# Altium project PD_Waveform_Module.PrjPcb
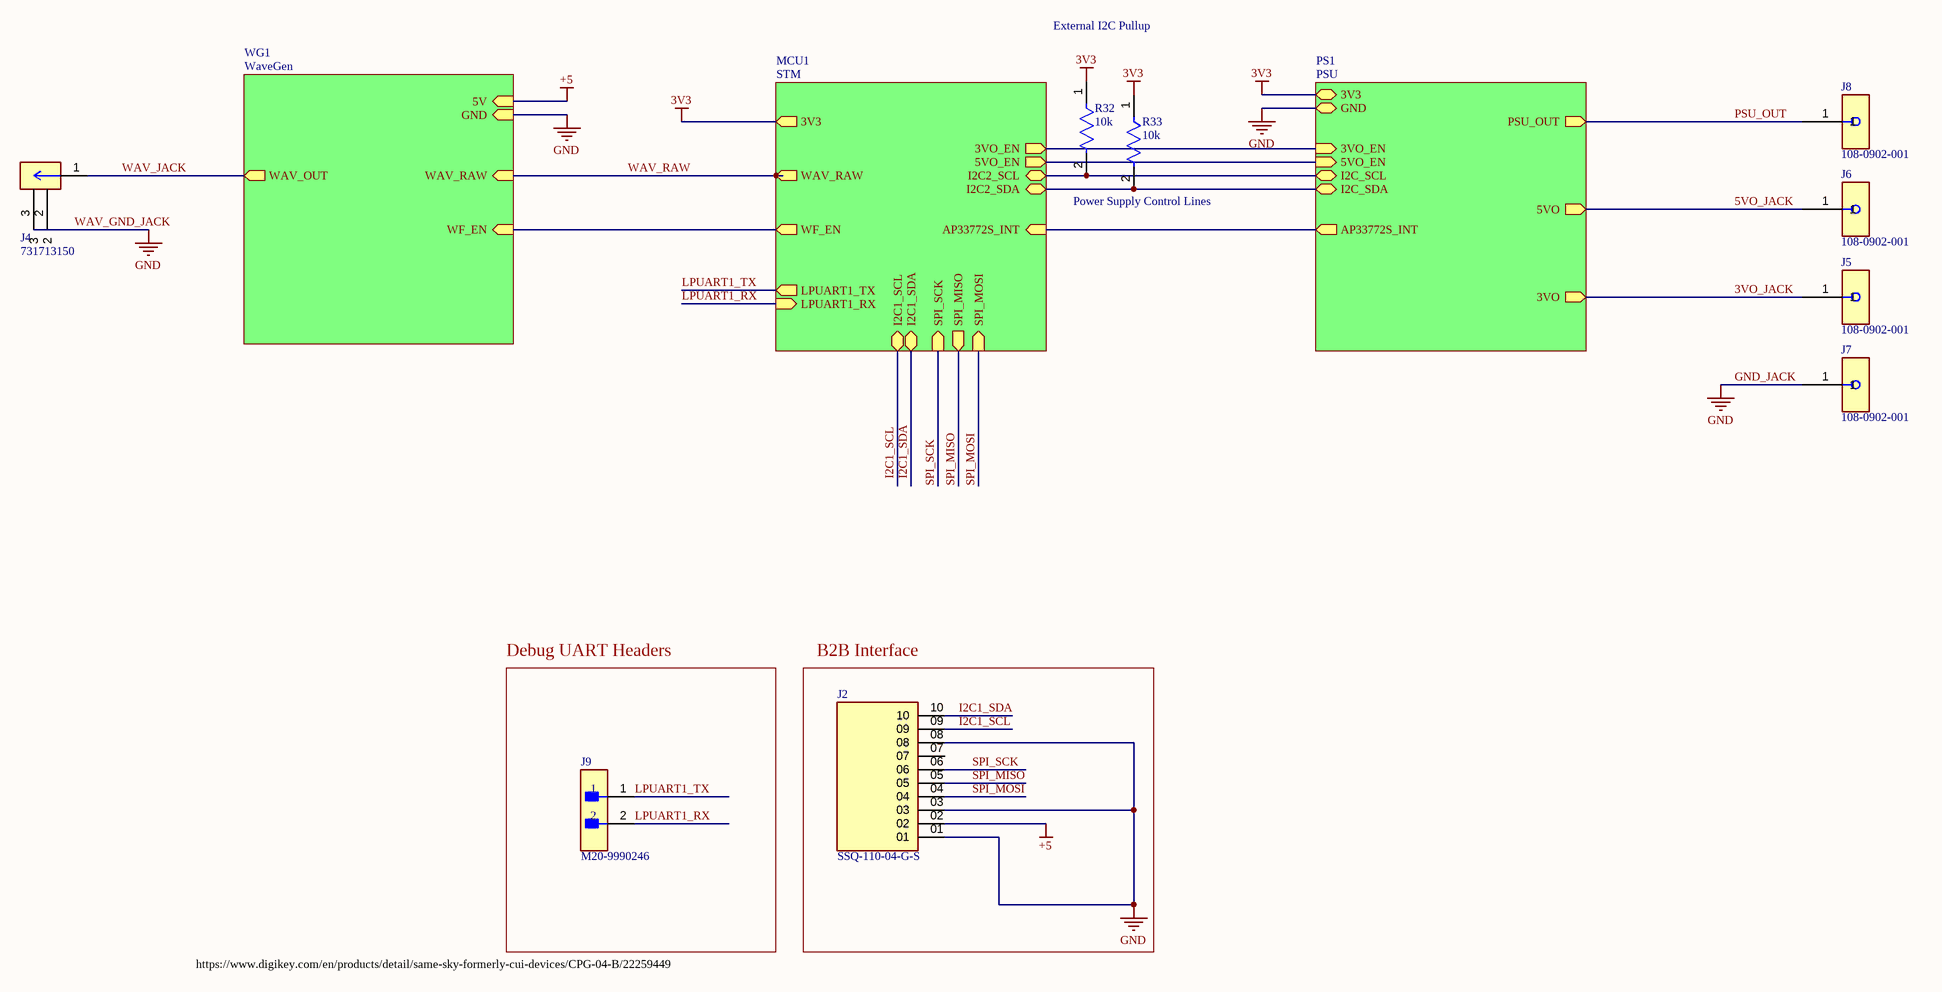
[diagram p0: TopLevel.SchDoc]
CAGE_CODE: ?????; CONTRACT_NUMBER: <CONTRACT NO>; DOC_NO_ASSY_DWG: <ASSY DWG NO>; DOC_NO_BOM: <BOM DOC NO>; DOC_NO_FAB_DWG: <FAB DWG NO>; DOC_NO_SCH_DWG: <SCH DWG NO>; PCB_2_DEC_TOL: +/-.01; PCB_3_DEC_TOL: +/-.010; PCB_ANG_TOL: +/-1/2; PCB_ASSEMBLY_NO: <PCB ASSY NO>; PCB_CHECKER: - -----; PCB_CHECKER_APP_DATE: --/--/----; PCB_DESIGNER: - -----; PCB_DESIGNER_APP_DATE: --/--/----; PCB_DWG_NO: <PCB DWG NO>; PCB_ENGINEER: - -----; PCB_ENGINEER_APP_DATE: --/--/----; PCB_PART_NUMBER: <PCB PN>; PCB_REV: A; SCH_REV: A
4 sheets, 96 parts. Net scope: hierarchical (ports join the sheet entries above them; power ports are global).
Board file: PCB1.PcbDoc
Sheets:
  TopLevel.SchDoc
    MCU1 = STM.SchDoc
    WG1 = WaveGen.SchDoc
    PS1 = PSU.SchDoc

## Sheet TopLevel.SchDoc
size 431 x 279 mm; SheetNumber: 1; SheetTotal: 4; ENG_APP_DATE: --/--/--; DSN_APP_DATE: --/--/--; CHK_APP_DATE: --/--/--

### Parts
J2  SSQ-110-04-G-S  [SAMTEC_SSQ-110-04-G-S]
J4  731713150  [CONN_731713150_MOL]
J5  108-0902-001  [FP-108-0902-001-MFG]
J6  108-0902-001  [FP-108-0902-001-MFG]
J7  108-0902-001  [FP-108-0902-001-MFG]
J8  108-0902-001  [FP-108-0902-001-MFG]
J9  M20-9990246  [FP-M20-9990246-MFG]
R32  10k  [FP-RC0603-0_55-IPC_C]
R33  10k  [FP-RC0603-0_55-IPC_C]

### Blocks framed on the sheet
Debug UART Headers: J9
B2B Interface: J2

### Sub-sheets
MCU1 = STM: 3VO_EN (out), 5VO_EN (out), I2C2_SCL (bidir), I2C2_SDA (bidir), AP33772S_INT (in), I2C1_SCL (bidir), I2C1_SDA (bidir), WAV_RAW (out), 3V3 (out), SPI_SCK (in), SPI_MISO (out), SPI_MOSI (in), LPUART1_TX (out), LPUART1_RX (in), WF_EN (out)
PS1 = PSU: I2C_SCL (bidir), AP33772S_INT (out), I2C_SDA (bidir), 3V3 (bidir), GND (bidir), 5VO_EN (in), 5VO (out), 3VO_EN (in), 3VO (out), PSU_OUT (out)
WG1 = WaveGen: WAV_OUT (out), WAV_RAW (in), 5V (in), GND (in), WF_EN (in)

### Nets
3V3: R32.1 R33.1 ; sheet MCU1/3V3, sheet PS1/3V3
+5: J2.02 ; sheet WG1/5V
GND: J2.01 J2.03 J2.08 J7.1 ; sheet WG1/GND, sheet PS1/GND  [also labelled GND_JACK, WAV_GND_JACK]
3VO_JACK: J5.1 ; sheet PS1/3VO
5VO_EN: sheet MCU1/5VO_EN, sheet PS1/5VO_EN
5VO_JACK: J6.1 ; sheet PS1/5VO  [project net 5VO]
I2C1_SCL: J2.09 ; sheet MCU1/I2C1_SCL
I2C1_SDA: J2.10 ; sheet MCU1/I2C1_SDA
I2C2_SCL: R32.2 ; sheet MCU1/I2C2_SCL, sheet PS1/I2C_SCL
I2C2_SDA: R33.2 ; sheet MCU1/I2C2_SDA, sheet PS1/I2C_SDA
LPUART1_RX: J9.2 ; sheet MCU1/LPUART1_RX
LPUART1_TX: J9.1 ; sheet MCU1/LPUART1_TX
PSU_OUT: J8.1 ; sheet PS1/PSU_OUT
SPI_MISO: J2.05 ; sheet MCU1/SPI_MISO
SPI_MOSI: J2.04 ; sheet MCU1/SPI_MOSI
SPI_SCK: J2.06 ; sheet MCU1/SPI_SCK
WAV_JACK: J4.1 ; sheet WG1/WAV_OUT
WAV_RAW: sheet MCU1/WAV_RAW, sheet WG1/WAV_RAW  [project net DAC1_OUT1]
NetQ6_1: sheet MCU1/WF_EN, sheet WG1/WF_EN
NetR9_1: sheet MCU1/AP33772S_INT, sheet PS1/AP33772S_INT
NetU1_39: sheet MCU1/3VO_EN, sheet PS1/3VO_EN

Not connected (* = marked no-connect by the designer): J2 07; J4 2 3

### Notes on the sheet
- External I2C Pullup
- Power Supply Control Lines
- https://www.digikey.com/en/products/detail/same-sky-formerly-cui-devices/CPG-04-B/22259449

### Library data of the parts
J2 = CMP-039-000000-3: Samtec Connector .1" pitch, long ahh pins
J4 = CMP-002-00084-4: JACK, BNC, 50OHM, R/A, THT; Connector Type: BNC Coaxial; Body Style: Right Angle J; MP: 73171-3150; MF: Molex
J5-J8 = CMP-002-00082-3: Banana Test Connector, 4mm, Jack, Panel Mount, 15 A, 7 kV, Tin Plated Contacts, Red; Gender: Female; Voltage Rating: 3.5kV; Max Current Rating: 15A
J9 = CMP-15831-000009-1: CONN HEADER VERT 2POS 2.54MM; Manufacturer: Harwin; Conn Gender: Male; Conn Orientation: Vertical; Number Of Contacts: 2; Current Rating: 3A
R32 R33 = CMP-2100-03664-2: RC0603FR-0710KL / RES 10K OHM 1% 1/10W 0603; Voltage Rating: 75V; Voltage Rating (DC): 50V; Resistance: 10kR; Power Rating: 100mW; Temperature Coefficient: 100ppm/°C

## Sheet STM.SchDoc
size A4; SheetNumber: 2; SheetTotal: 4
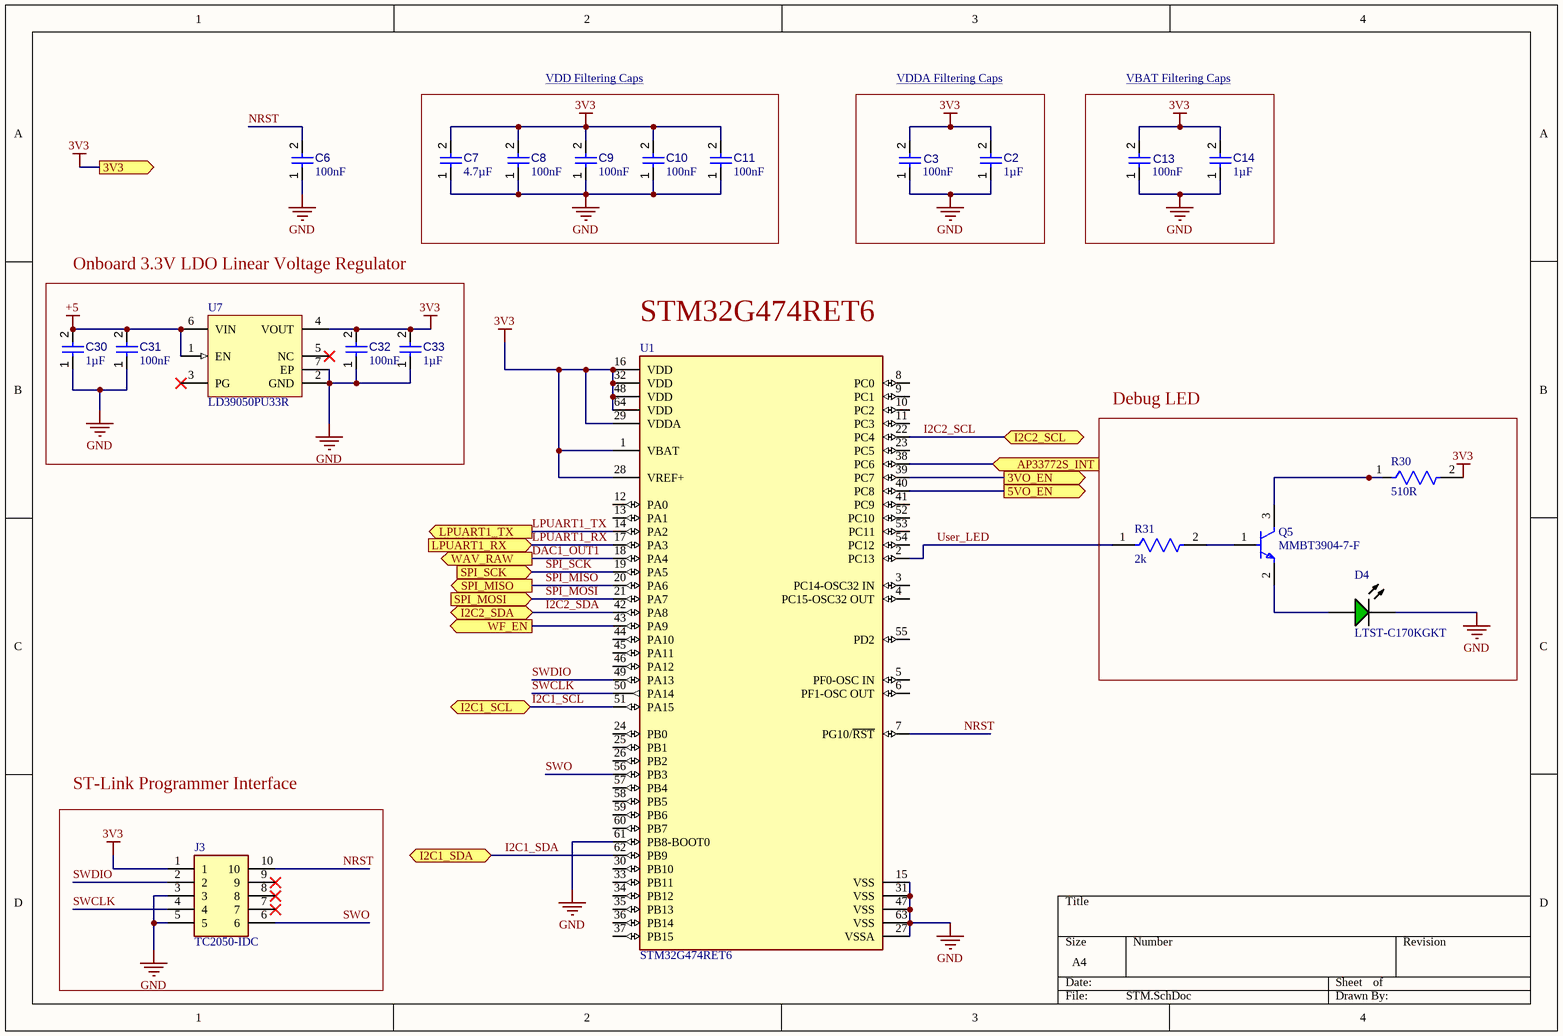
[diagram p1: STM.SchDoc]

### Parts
C2  value 1µF  [CAPC1608X90X35ML15T15]  (hidden comment: Capacitor 1uF +/- 10% 16V 0603)
C3  value 100nF  [CAPC0402(1005)60_L]  (hidden comment: Capacitor 100nF +/-20% 10V 0402)
C6  value 100nF  [CAPC1005X56X25LL10T15]  (hidden comment: Capacitor 0.1 uF +/- 5% 16 V 0402)
C7  value 4.7µF  [CAPC0603(1608)100_L]  (hidden comment: Capacitor 4.7µF +/-20% 10V 0603)
C8  value 100nF  [CAPC0402(1005)60_L]  (hidden comment: Capacitor 100nF +/-20% 10V 0402)
C9  value 100nF  [CAPC0402(1005)60_L]  (hidden comment: Capacitor 100nF +/-20% 10V 0402)
C10  value 100nF  [CAPC0402(1005)60_L]  (hidden comment: Capacitor 100nF +/-20% 10V 0402)
C11  value 100nF  [CAPC0402(1005)60_L]  (hidden comment: Capacitor 100nF +/-20% 10V 0402)
C13  value 100nF  [CAPC0402(1005)60_L]  (hidden comment: Capacitor 100nF +/-20% 10V 0402)
C14  value 1µF  [CAPC1608X90X35ML15T15]  (hidden comment: Capacitor 1uF +/- 10% 16V 0603)
C30  value 1µF  [CAPC1608X90X35ML15T15]  (hidden comment: Capacitor 1uF +/- 10% 16V 0603)
C31  value 100nF  [CAPC0402(1005)60_L]  (hidden comment: Capacitor 100nF +/-20% 10V 0402)
C32  value 100nF  [CAPC0402(1005)60_L]  (hidden comment: Capacitor 100nF +/-20% 10V 0402)
C33  value 1µF  [CAPC1608X90X35ML15T15]  (hidden comment: Capacitor 1uF +/- 10% 16V 0603)
D4  LTST-C170KGKT  [LTST-LTST-C170KGKT-2_V]
J3  TC2050-IDC  [TAG-CONNECT_TC2050-IDC]
Q5  MMBT3904-7-F  [FP-SOT23-IPC_A]
R30  510R  [FP-RMCF0603-IPC_B]
R31  2k  [FP-RMCF0603-IPC_C]
U1  STM32G474RET6  [FP-LQFP64-5W-MFG]
U7  LD39050PU33R  [DFN6D_M]

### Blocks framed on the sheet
VDD Filtering Caps: C7-C11
VDDA Filtering Caps: C2 C3
VBAT Filtering Caps: C13 C14
Onboard 3.3V LDO Linear Voltage Regulator: C30-C33 U7
Debug LED: D4 Q5 R30 R31
ST-Link Programmer Interface: J3

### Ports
3V3 (out), 3VO_EN (out), 5VO_EN (out), AP33772S_INT (in), I2C1_SCL (bidir), I2C1_SDA (bidir), I2C2_SCL (bidir), I2C2_SDA (bidir), LPUART1_RX (in), LPUART1_TX (out), SPI_MISO (out), SPI_MOSI (in), SPI_SCK (in), WAV_RAW (out), WF_EN (out)

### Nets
3V3: C2.2 C3.2 C7.2 C8.2 C9.2 C10.2 C11.2 C13.2 C14.2 C32.2 C33.2 J3.1 R30.2 U1.1(VBAT) U1.16(VDD) U1.28(VREF+) U1.29(VDDA) U1.32(VDD) U1.48(VDD) U1.64(VDD) U7.4(VOUT) ; port 3V3
+5: C30.2 C31.2 U7.1(EN) U7.6(VIN)
GND: C2.1 C3.1 C6.1 C7.1 C8.1 C9.1 C10.1 C11.1 C13.1 C14.1 C30.1 C31.1 C32.1 C33.1 D4.1(K) J3.3 J3.5 U1.15(VSS) U1.27(VSSA) U1.31(VSS) U1.47(VSS) U1.61(PB8-BOOT0) U1.63(VSS) U7.2(GND) U7.7(EP)
5VO_EN: U1.40(PC8) ; port 5VO_EN
DAC1_OUT1: U1.18(PA4) ; port WAV_RAW
I2C1_SCL: U1.51(PA15) ; port I2C1_SCL
I2C1_SDA: U1.62(PB9) ; port I2C1_SDA
I2C2_SCL: U1.22(PC4) ; port I2C2_SCL
I2C2_SDA: U1.42(PA8) ; port I2C2_SDA
LPUART1_RX: U1.17(PA3) ; port LPUART1_RX
LPUART1_TX: U1.14(PA2) ; port LPUART1_TX
NRST: C6.2 J3.10 U1.7(PG10/~{RST})
SPI_MISO: U1.20(PA6) ; port SPI_MISO
SPI_MOSI: U1.21(PA7) ; port SPI_MOSI
SPI_SCK: U1.19(PA5) ; port SPI_SCK
SWCLK: J3.4 U1.50(PA14)
SWDIO: J3.2 U1.49(PA13)
SWO: J3.6 U1.56(PB3)
User_LED: R31.1 U1.2(PC13)
NetD4_2: D4.2(A) Q5.2(E)
NetQ5_1: Q5.1(B) R31.2
NetQ5_3: Q5.3(C) R30.1
NetQ6_1: U1.43(PA9) ; port WF_EN
NetR9_1: U1.38(PC6) ; port AP33772S_INT
NetU1_39: U1.39(PC7) ; port 3VO_EN

Not connected (* = marked no-connect by the designer): J3 7* 8* 9*; U1 3(PC14-OSC32_IN) 4(PC15-OSC32_OUT) 5(PF0-OSC_IN) 6(PF1-OSC_OUT) 8(PC0) 9(PC1) 10(PC2) 11(PC3) 12(PA0) 13(PA1) 23(PC5) 24(PB0) 25(PB1) 26(PB2) 30(PB10) 33(PB11) 34(PB12) 35(PB13) 36(PB14) 37(PB15) 41(PC9) 44(PA10) 45(PA11) 46(PA12) 52(PC10) 53(PC11) 54(PC12) 55(PD2) 57(PB4) 58(PB5) 59(PB6) 60(PB7); U7 3(PG)* 5(NC)*

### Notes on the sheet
- (near U1) STM32G474RET6

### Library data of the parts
C2 C14 C30 C33 = CMP-001-00004-6: Chip Capacitor, 1 uF, +/- 10%, 16 V, 0603 (1608 Metric); Capacitor Type: Ceramic
C3 C8-C11 C13 C31 C32 = CMP-001-00061-3: Chip Capacitor, 100nF +/-20%, 10V, 0402, Thickness 0.6 mm; Tolerance: 20%
C6 = CMP-001-00001-6: Chip Capacitor, 0.1 uF, +/- 5%, 16 V, 0402 (1005 Metric); Capacitor Type: Ceramic; Voltage Rating: 16V
C7 = CMP-001-00076-4: Chip Capacitor, 4.7µF +/-20%, 10V, 0603, Thickness 1 mm; Tolerance: 10%
D4 = CMP-2000-06620-1: Ultra Bright AlInGaP Chip LED, 75 mW, -55 to 85 degC, 2-Pin SMD (0805), RoHS, Tape and Reel; Manufacturer: Lite-On; Forward Current: 30mA; Power Dissipation Max: 75mW; Emitting Color: YellowGreen; Type: Uni-Color; Forward Voltage: 2.4V; Dominant Wave Length: 571nm; Test Current (It): 20mA; Product Length (mm): 2mm; Peak Wavelength: 574nm; Power Dissipation: 75W; Product Depth (mm): 1.25mm; DELETED: Compliant; High Brightness: Yes; Product Height (mm): 1.1mm; Luminous Intensity: 35mcd; Shape Type: Rectangular; Chip Material: AlGaInP; Viewing Angle: 130deg; Number of  Elements: 1; Reverse Voltage: 5V; Rad Hardened: No
J3 = CMP-035-000000-1: Cbl Plug-Of-Nails 10-Pin w/Legs
Q5 = CMP-2000-04931-2: TRANS NPN 40V 0.2A SMD SOT23-3; Frequency: 300MHz; Power Dissipation: 350mW; Element Configuration: Single; Max Power Dissipation: 300mW; Max Collector Current: 200mA; Collector Emitter Saturation Voltage: 300mV; Number of Elements: 1; hFE Min: 100; Collector Base Voltage (VCBO): 60V; Emitter Base Voltage (VEBO): 6V
R30 = CMP-26527-005064-1: RMCF0603JG510R / 510Ω ±5% 0.1W 0603 Thick Film Chip Resistor AEC-Q200 compliant; Temperature Coefficient: 200ppm/°C; Max Power Dissipation: 100mW
R31 = CMP-26527-003372-1: RMCF0603FG2K00 / 2kΩ ±1% 0.1W 0603 Thick Film Chip Resistor AEC-Q200 compliant; Resistance: 2kR; Temperature Coefficient: 100ppm/°C
U1 = CMP-12105-000051-1: MAINSTREAM ARM CORTEX-M4 CORE WI; Manufacturer: STMicroelectronics; Ram Size: 128KBytes; Interface: I2C,SPI,UART,USART,CAN,USB,LIN,IrDA,I2S,SMBus,Other; Number Of I2C Channels: 4; Number Of A/D Converters: 5; Number Of Timers/Counters: 14; Number Of I/Os: 52; Max Supply Voltage: 3.6V; Memory Size: 512KBytes; Number Of Adc Channels: 26; Number Of Cores: 1; Min Supply Voltage: 1.71V; Max Junction Temp: +105°C; Standoff Height: 0.05mm; Number Of Uart Channels: 6; Number Of Spi Channels: 3; Frequency: 170MHz; Data Bus Width: 32bits; Memory Type: FLASH; Number Of Pwm Channels: 32
U7 = CMP-019-00050-2: 500 mA low quiescent current low noise voltage regulator; Max Supply Voltage: 5.5V; Output Current: 500mA; Dropout Voltage: 400mV; Output Voltage: 3.3V

## Sheet WaveGen.SchDoc
size A4; SheetNumber: 3; SheetTotal: 4
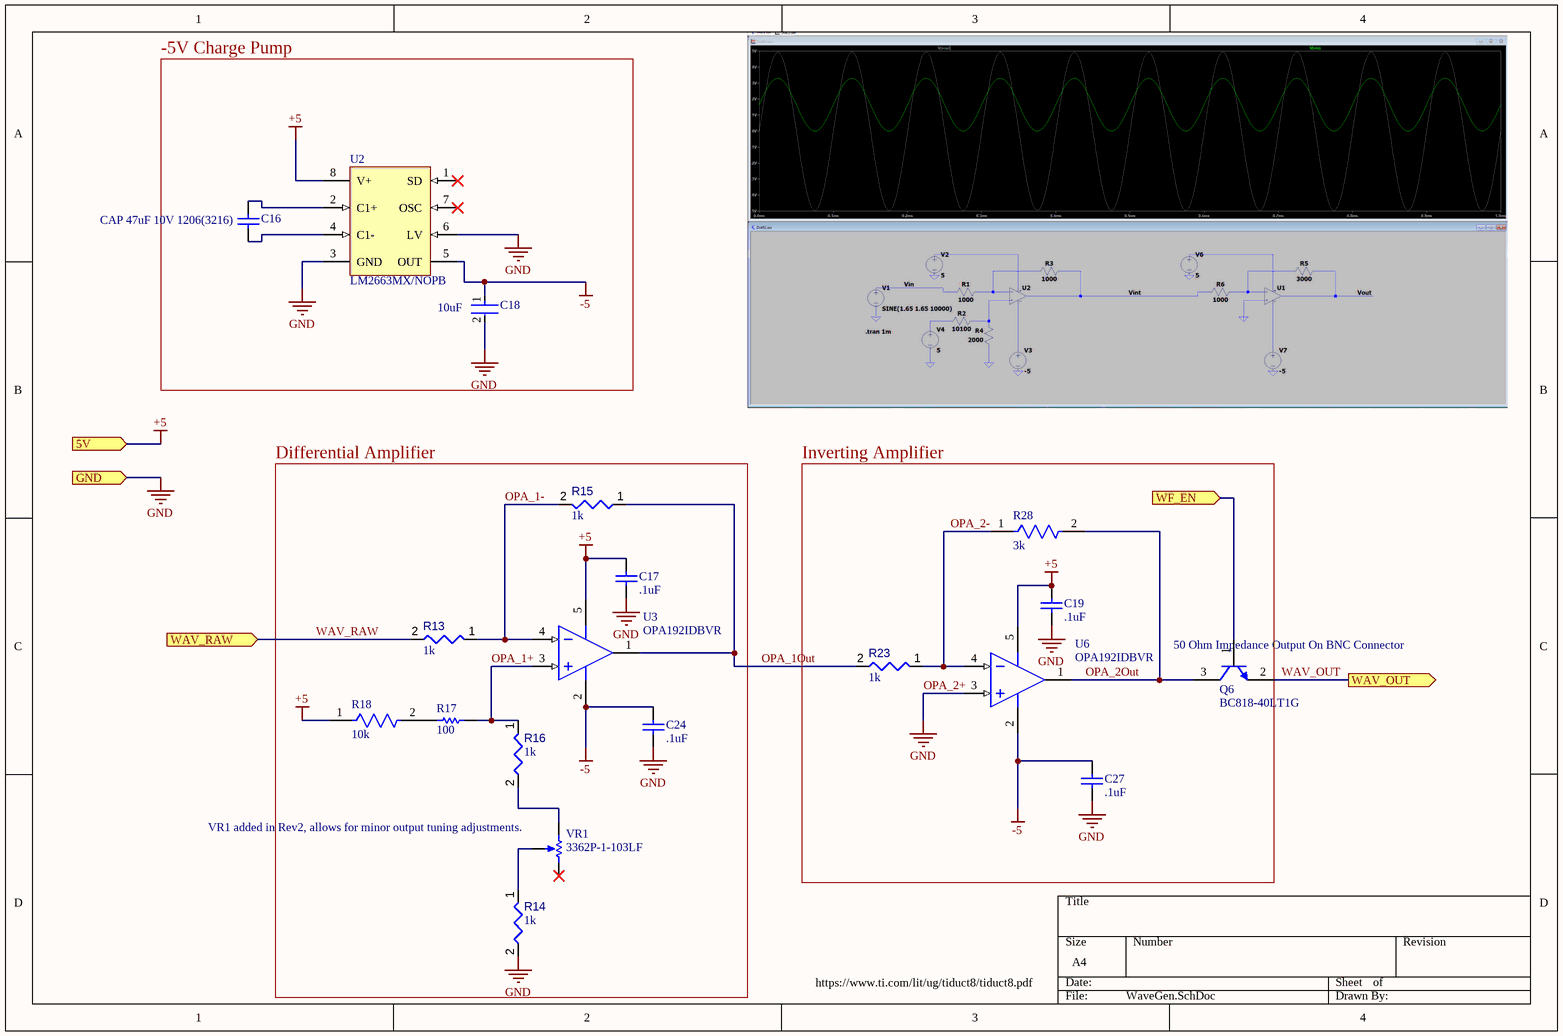
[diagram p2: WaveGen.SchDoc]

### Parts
C16  CAP 47uF 10V 1206(3216)  [CAPC1206(3216)190_N]
C17  .1uF  [CAPC1608X90X35NL15T15]
C18  10uF  [FP-GRM188-0_2-IPC_B]
C19  .1uF  [CAPC1608X90X35NL15T15]
C24  .1uF  [CAPC1608X90X35NL15T15]
C27  .1uF  [CAPC1608X90X35NL15T15]
Q6  BC818-40LT1G  [ONSC-SOT-23-3-318-08_V]
R13  value 1k  [RESC1608X55X25ML10T15]  (hidden comment: Resistor 1k +/-1% 0603 100 mW)
R14  value 1k  [RESC1608X55X25ML10T15]  (hidden comment: Resistor 1k +/-1% 0603 100 mW)
R15  value 1k  [RESC1608X55X25ML10T15]  (hidden comment: Resistor 1k +/-1% 0603 100 mW)
R16  value 1k  [RESC1608X55X25ML10T15]  (hidden comment: Resistor 1k +/-1% 0603 100 mW)
R17  100  [RESC1609X50X30LL10T20]
R18  10k  [FP-RC0603-0_55-IPC_C]
R23  value 1k  [RESC1608X55X25ML10T15]  (hidden comment: Resistor 1k +/-1% 0603 100 mW)
R28  3k  [FP-RMCF0603-IPC_A]
U2  LM2663MX/NOPB  [D0008A_M]
U3  OPA192IDBVR  [DBV0005A_L]
U6  OPA192IDBVR  [DBV0005A_L]
VR1  3362P-1-103LF  [BOUR-3362P]

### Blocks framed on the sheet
-5V Charge Pump: C16 C18 U2
Differential Amplifier: C17 C24 R13-R18 U3 VR1
Inverting Amplifier: C19 C27 Q6 R23 R28 U6

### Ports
5V (in), GND (in), WAV_OUT (out), WAV_RAW (in), WF_EN (in)

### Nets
+5: C17.2 C19.2 R18.1 U2.8(V+) U3.5(V+) U6.5(V+) ; port 5V
-5: C18.1 C24.2 C27.2 U2.5(OUT) U3.2(V-) U6.2(V-)
GND: C17.1 C18.2 C19.1 C24.1 C27.1 R14.2 U2.3(GND) U2.6(LV) U6.3(IN+) ; port GND  [also labelled OPA_2+]
OPA_1+: R16.1 R17.2 U3.3(IN+)
OPA_1-: R13.1 R15.2 U3.4(IN-)
OPA_1Out: R15.1 R23.2 U3.1(OUT)
OPA_2-: R23.1 R28.1 U6.4(IN-)
OPA_2Out: Q6.3(C) R28.2 U6.1(OUT)
WAV_OUT: Q6.2(E) ; port WAV_OUT  [project net WAV_JACK]
WAV_RAW: R13.2 ; port WAV_RAW  [project net DAC1_OUT1]
NetC16_1: C16.1 U2.4(C1-)
NetC16_2: C16.2 U2.2(C1+)
NetQ6_1: Q6.1(B) ; port WF_EN
NetR14_1: R14.1 VR1.2(S)
NetR16_2: R16.2 VR1.1(CCW)
NetR17_1: R17.1 R18.2

Not connected (* = marked no-connect by the designer): U2 1(SD)* 7(OSC)*; VR1 3(CW)*

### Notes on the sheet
- (near Q6) 50 Ohm Impedance Output On BNC Connector
- (near VR1) VR1 added in Rev2, allows for minor output tuning adjustments.
- https://www.ti.com/lit/ug/tiduct8/tiduct8.pdf

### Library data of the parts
C16 = CMP-1037-05002-1: CAP 47uF 10V ±20% 1206 (3216 Metric) Thickness 1.9mm SMD; Case-Metric: 3216; Case-EIA: 1206; Tolerance: Â±20%
C17 C19 C24 C27 = CMP-2006-02299-1: C0603C104K4RAC7013; Manufacturer: Kemet
C18 = CMP-06035-020296-1: Chip Multilayer Ceramic Capacitors for General Purpose, 0603, 10uF, X7R, 15%, 10%, 10V / GRM188Z71A106KA73J
Q6 = CMP-1048-00772-1: General Purpose Transistor, NPN Silicon, 3-Pin SOT-23, Pb-Free, Tape and Reel; Manufacturer: On Semiconductor; fT Min (MHz): 100; IC Continuous (A): 0.5
R13-R16 R23 = CMP-009-00014-5: Chip Resistor, 1 KOhm, +/-1%, 0.1 W, -55 to 155 degC, 0603 (1608 Metric); Voltage Rating: 50V; Power: 100mW; Tolerance: 1%
R17 = CMP-2000-03826-1: CRCW0603100RFKTA; Manufacturer: Vishay Dale
R18 = CMP-2100-03664-2: as R32 on sheet TopLevel
R28 = CMP-26527-007404-1: RMCF0603JG3K00 / 3kΩ ±5% 0.1W 0603 Thick Film Chip Resistor AEC-Q200 compliant; Max Power Dissipation: 100mW; Resistance: 3kR; Temperature Coefficient: 200ppm/°C
U2 = CMP-0065-00039-3: Switched Capacitor Voltage Converter, 8-pin Narrow SOIC, Pb-Free; Manufacturer: Texas Instruments; PowerWise: N; PackageTopMarking: NSZXTT*LM26*63M; CompType: Switch Caps
U3 U6 = CMP-0272-04163-2: Precision, Rail-to-Rail Input/Output, Low Offset Voltage, Low Input Bias Current Op Amp with E-trim, 4.5 to 36 V, -40 to 125 degC, 5-Pin SOT-23 (DBV), Green (RoHS & no Sb/Br), Tape and Reel; VS Max: 36 V; Channel: 1; VS Min: 4.5 V; Slew Rate: 20 V/us
VR1 = CMP-1747-00004-1: Square Trimpot(R) Trimming Potentiometer, 10 KOhm, 300 V, -55 to 125 degC, 3-Pin THD, RoHS, Tube; Voltage Rating: 220 mV; Power Rating: 1 W; Tolerance: 1%; Resistance: 50 mohm

## Sheet PSU.SchDoc: AP33772S Adjustable Power Supply
size B; Author: Cameron Trumpy; SheetNumber: 4; SheetTotal: 4
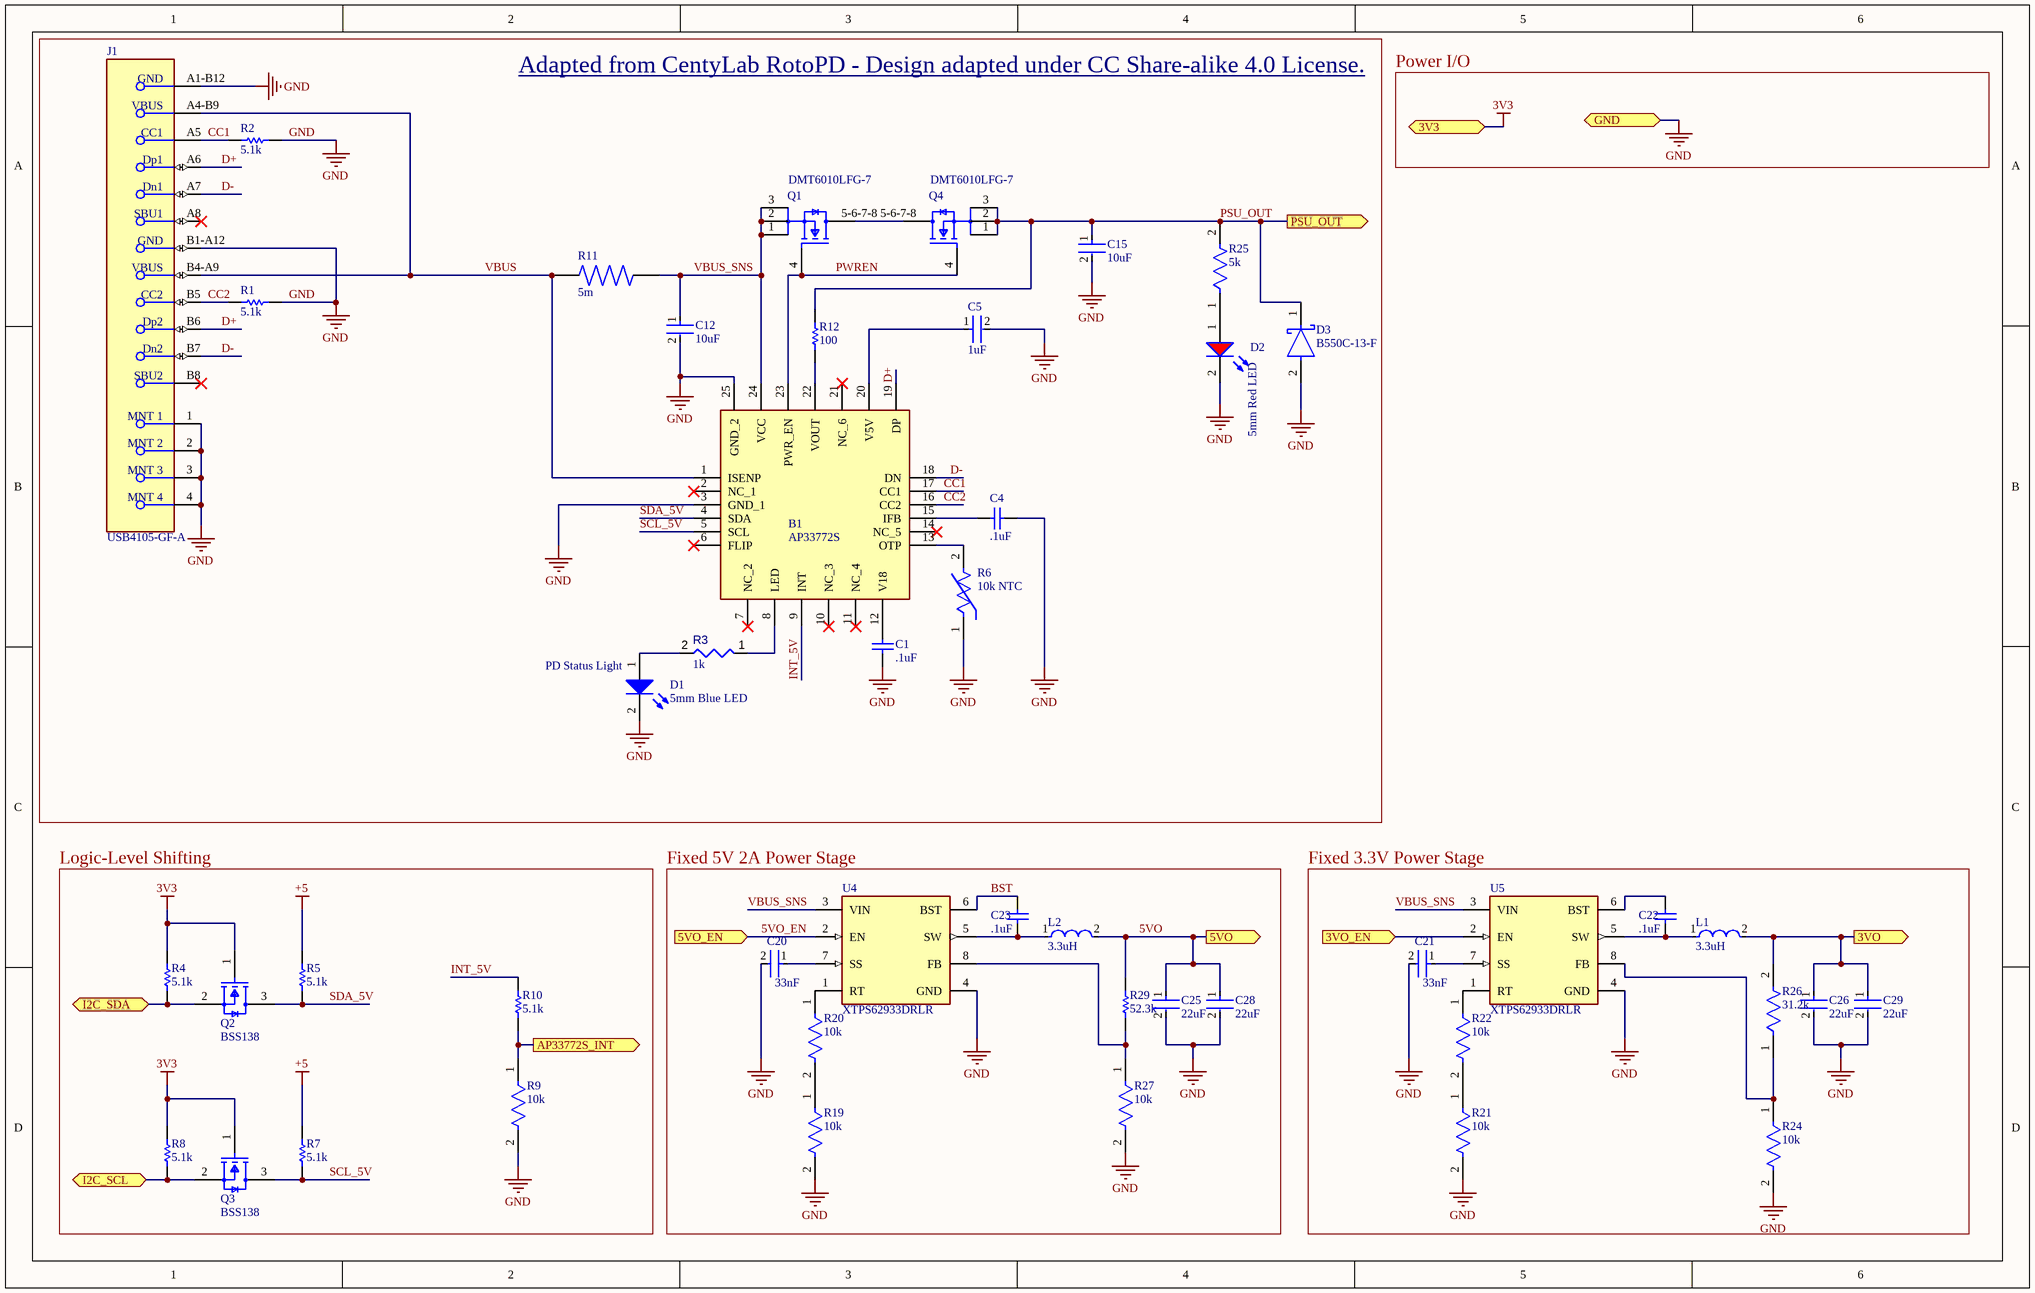
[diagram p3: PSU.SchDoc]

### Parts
B1  AP33772S  [AP33772SDKZ13FA01]
C1  .1uF  [CAPC1608X90X35NL15T15]
C4  .1uF  [CAPC1608X90X35NL15T15]
C5  1uF  [FP-CC0603-DA-MFG]
C12  10uF  [FP-C3216-160-0_2-IPC_C]
C15  10uF  [FP-C3216-160-0_2-IPC_C]
C20  33nF  [FP-C0603C333J4REC7411-MFG]
C21  33nF  [FP-C0603C333J4REC7411-MFG]
C22  .1uF  [CAPC1608X90X35NL15T15]
C23  .1uF  [CAPC1608X90X35NL15T15]
C25  22uF  [FP-GRM188-0_2-IPC_C]
C26  22uF  [FP-GRM188-0_2-IPC_C]
C28  22uF  [FP-GRM188-0_2-IPC_C]
C29  22uF  [FP-GRM188-0_2-IPC_C]
D1  5mm Blue LED  [WL-TMRC_D5.9H8.7]
D2  5mm Red LED  [WL-TMRC_D5.9H8.7]
D3  B550C-13-F  [FP-SMC-MFG]
J1  USB4105-GF-A  [FP-USB4105-GF-A-MFG]
L1  3.3uH  [FP-NR5040-H_4_1-MFG]
L2  3.3uH  [FP-NR5040-H_4_1-MFG]
Q1  DMT6010LFG-7  [FP-PowerDI3333-8-MFG]
Q2  BSS138  [FP-318-08-IPC_B]
Q3  BSS138  [FP-318-08-IPC_B]
Q4  DMT6010LFG-7  [FP-PowerDI3333-8-MFG]
R1  5.1k  [RESC1608X55X25ML10T15]
R2  5.1k  [RESC1608X55X25ML10T15]
R3  value 1k  [RESC1608X55X25ML10T15]  (hidden comment: Resistor 1k +/-1% 0603 100 mW)
R4  5.1k  [RESC1608X55X25ML10T15]
R5  5.1k  [RESC1608X55X25ML10T15]
R6  10k NTC  [FP-NC_18-0_15-IPC_B]
R7  5.1k  [RESC1608X55X25ML10T15]
R8  5.1k  [RESC1608X55X25ML10T15]
R9  10k  [FP-RC0603-0_55-IPC_C]
R10  5.1k  [RESC1608X55X25ML10T15]
R11  value 5m  [RES_ERJ6LWFR005V]  (hidden comment: ERJ6LWFR005V)
R12  100  [RESC2013X60X40ML20T25]
R19  10k  [FP-RC0603-0_55-IPC_C]
R20  10k  [FP-RC0603-0_55-IPC_C]
R21  10k  [FP-RC0603-0_55-IPC_C]
R22  10k  [FP-RC0603-0_55-IPC_C]
R24  10k  [FP-RC0603-0_55-IPC_C]
R25  5k  [FP-RT1206-0_65-MFG]
R26  31.2k  [FP-TFCR1206-IPC_B]
R27  10k  [FP-RC0603-0_55-IPC_C]
R29  52.3k  [RESC1608X55X25LL10T15]
U4  XTPS62933DRLR  [FP-DRL0008A-MFG]
U5  XTPS62933DRLR  [FP-DRL0008A-MFG]

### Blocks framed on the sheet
PD Status Light: B1 C1 C4 C5 C12 C15 D1-D3 J1 Q1 Q4 R1-R3 R6 R11 R12 R25
Logic-Level Shifting: Q2 Q3 R4 R5 R7-R10
Fixed 5V 2A Power Stage: C20 C23 C25 C28 L2 R19 R20 R27 R29 U4
Fixed 3.3V Power Stage: C21 C22 C26 C29 L1 R21 R22 R24 R26 U5

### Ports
3V3 (bidir), 3VO (out), 3VO_EN (in), 5VO (out), 5VO_EN (in), AP33772S_INT (out), GND (bidir), I2C_SCL (bidir), I2C_SDA (bidir), PSU_OUT (out)

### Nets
3V3: Q2.1(G) Q3.1(G) R4.2 R8.2 ; port 3V3
+5: R5.2 R7.2
GND: B1.3(GND_1) B1.25(GND_2) C1.2 C4.1 C5.2 C12.2 C15.2 C20.2 C21.2 C25.2 C26.2 C28.2 C29.2 D1.2(K) D2.2(K) D3.2(A) J1.1(MNT_1) J1.2(MNT_2) J1.3(MNT_3) J1.4(MNT_4) J1.A1-B12(GND) J1.B1-A12(GND) R1.1 R2.1 R6.1 R9.2 R19.2 R21.2 R24.2 R27.2 U4.4(GND) U5.4(GND) ; port GND
3VO_JACK: C26.1 C29.1 L1.2 R26.2 ; port 3VO
5VO: C25.1 C28.1 L2.2 R29.2 ; port 5VO
5VO_EN: U4.2(EN) ; port 5VO_EN
BST: C23.1 U4.6(BST)
CC1: B1.17(CC1) J1.A5(CC1) R2.2
CC2: B1.16(CC2) J1.B5(CC2) R1.2
D+: B1.19(DP) J1.A6(Dp1) J1.B6(Dp2)
D-: B1.18(DN) J1.A7(Dn1) J1.B7(Dn2)
I2C2_SCL: Q3.2(S) R8.1 ; port I2C_SCL
I2C2_SDA: Q2.2(S) R4.1 ; port I2C_SDA
INT_5V: B1.9(INT) R10.2
PSU_OUT: C15.1 D3.1(C) Q4.1(S) Q4.2(S) Q4.3(S) R12.2 R25.2 ; port PSU_OUT
PWREN: B1.23(PWR_EN) Q1.4(G) Q4.4(G)
SCL_5V: B1.5(SCL) Q3.3(D) R7.1
SDA_5V: B1.4(SDA) Q2.3(D) R5.1
VBUS: B1.1(ISENP) J1.A4-B9(VBUS) J1.B4-A9(VBUS) R11.1
VBUS_SNS: B1.24(VCC) C12.1 Q1.1(S) Q1.2(S) Q1.3(S) R11.2 U4.3(VIN) U5.3(VIN)
NetB1_8: B1.8(LED) R3.1
NetB1_12: B1.12(V18) C1.1
NetB1_13: B1.13(OTP) R6.2
NetB1_15: B1.15(IFB) C4.2
NetB1_20: B1.20(V5V) C5.1
NetB1_22: B1.22(VOUT) R12.1
NetC20_1: C20.1 U4.7(SS)
NetC21_1: C21.1 U5.7(SS)
NetC22_1: C22.1 U5.6(BST)
NetC22_2: C22.2 L1.1 U5.5(SW)
NetC23_2: C23.2 L2.1 U4.5(SW)
NetD1_1: D1.1(A) R3.2
NetD2_1: D2.1(A) R25.1
NetQ1_5-6-7-8: Q1.5-6-7-8(D) Q4.5-6-7-8(D)
NetR9_1: R9.1 R10.1 ; port AP33772S_INT
NetR19_1: R19.1 R20.2
NetR20_1: R20.1 U4.1(RT)
NetR21_1: R21.1 R22.2
NetR22_1: R22.1 U5.1(RT)
NetR24_1: R24.1 R26.1 U5.8(FB)
NetR27_1: R27.1 R29.1 U4.8(FB)
NetU1_39: U5.2(EN) ; port 3VO_EN

Not connected (* = marked no-connect by the designer): B1 2(NC_1)* 6(FLIP)* 7(NC_2)* 10(NC_3)* 11(NC_4)* 14(NC_5)* 21(NC_6)*; J1 A8(SBU1)* B8(SBU2)*

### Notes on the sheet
- Adapted from CentyLab RotoPD - Design adapted under CC Share-alike 4.0 License. <https://github.com/CentyLab/RotoPD?tab=License-1-ov-file>
- Power I/O

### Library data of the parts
B1 = CMP-019-00051-3: USB, Type-C Controller PMIC W-QFN4040-24 (Type A1); Manufacturer_Name: Diodes Incorporated; Geometry.Height: 0.8mm
C1 C4 C22 C23 = CMP-2006-02299-1: C0603C104K4RAC7013; Manufacturer: Kemet
C5 = CMP-03422-000857-1: CC0603MRX5R8BB105 / CAP CER 1UF 25V X5R 0603; Manufacturer: YAGEO; Tolerance: 0.2; Material: Ceramic; Temperature Coefficient: 15%
C12 C15 = CMP-2000-06047-2: C3216X7R1V106K160AC / Multilayer Ceramic Capacitors 10uF ±10% 35V X7R SMD 1206
C20 C21 = CMP-03020-034693-1: C0603C333J4REC7411 / CAP CER 0603 33NF 16V X7R 5%
C25 C26 C28 C29 = CMP-2000-06337-3: GRM188R61A226ME15D / Chip Multilayer Ceramic Capacitors for General Purpose, 0603, 22uF, X5R, 15%, 20%, 10V
D1 = CMP-004-00031-2: 151051BS04000 / Single Color LED, Blue, Diffused, T-1 3/4, 4.9mm; NexarPartId: 29717812; Dominant Wavelength: 470nm; Test Current: 20mA; Viewing Angle: 40°; Luminous Intensity: 500mcd; Forward Current: 100mA; Max Reverse Voltage (DC): 5V; Forward Voltage: 3.2V; Lens Style: Circular, Diffused, Round; Peak Wavelength: 465nm
D2 = CMP-007-00039-1: 151051RS11000 / WL-TMRC Red Color Diffused 5 mm Round Through Hole LED; Forward Voltage: 2.1V; Forward Current: 100mA
D3 = CMP-2000-05906-2: DIODE SCHOTTKY 50V 5A SMC; Peak Reverse Current: 500uA; Peak Non-Repetitive Surge Current: 100A; Capacitance: 300pF; Forward Voltage: 700mV; Polarity: Standard; Element Configuration: Single
J1 = CMP-245163-000001-1: CONN RCPT USB2.0 TYPEC 5A; Manufacturer: GCT; Voltage Rating: 20V; Is Female: yes; Current Rating: 5/6.25/1.25/0.25A; Number Of Contacts: 16; Conn Orientation: Right Angle
L1 L2 = CMP-14484-001090-1: NRS5040T3R3NMGJ / SMD Power Inductors 3.3uH ±30% 3.3A 35.1mΩ; DC Resistance (DCR): 27mR; Core Material: Ferrite; Shielding: Shielded; Self Resonant Frequency: 32MHz; Test Frequency: 100kHz; Saturation Current: 4A
Q1 Q4 = CMP-12801-000078-1: MOSFET N-CH 60V 13A POWERDI; Fall Time: 9.7ns; Turn-On Delay Time: 5.7ns; Capacitance: 2.09E-09F; Continuous Drain Current (ID): 30A; Element Configuration: Single; Rise Time: 4.3ns; Max Power Dissipation: 2.2W; Rds On Max: 7.5mR; Drain to Source Resistance: 7.8mR; Input Capacitance: 2.09nF; Gate to Source Voltage (Vgs): 20V; Turn-Off Delay Time: 23.4ns; Number of Channels: 1
Q2 Q3 = CMP-07173-000101-1: MOSFET N-CH 50V 220MA SOT-23; Turn-Off Delay Time: 20ns; Element Configuration: Single; Rds On Max: 3.5R; Gate to Source Voltage (Vgs): 20V; Threshold Voltage: 1.3V; Number of Elements: 1; Power Dissipation: 360mW; Rise Time: 9ns; Turn-On Delay Time: 2.5ns; Input Capacitance: 27pF; On-State Resistance: 6R
R1 R2 R4 R5 R7 R8 R10 = CMP-2000-04091-1: RC0603FR-075K1L; Manufacturer: Yageo
R3 = CMP-009-00014-5: as R13 on sheet WaveGen
R6 = CMP-06022-000566-1: NCG18XH103F0SRB / NTC Thermistor 10kΩ 1% SMD  0201 (0603 Metric)
R9 R19-R22 R24 R27 = CMP-2100-03664-2: as R32 on sheet TopLevel
R11 = CMP-009-00179-1: 5 mOhms Â±1% 0.5W, 1/2W Chip Resistor 0805 (2012 Metric) Automotive AEC-Q200, Current Sense Thick Film; MP: ERJ-6LWFR005V; MF: Panasonic Electronic
R12 = CMP-2001-00580-1: ERA6AEB101V; Manufacturer: Panasonic
R25 = CMP-03412-001731-1: RT1206BRD075KL / RES SMD 5K OHM 0.1% 1/4W 1206; Manufacturer: Yageo; Resistance: 5kΩ; Value: 5kΩ; Power Rating: 0.25W; Voltage Rating: 200V; Temperature Coefficient: 25ppm/°C
R26 = CMP-250906-096381-1: RES Thin Film, 31.2kΩ, 0.1%, 0.25W, 50ppm/°C, 1206
R29 = CMP-1012-00705-2: RC0603FR-0752K3L; Manufacturer: Yageo
U4 U5 = CMP-04918-000610-1: 3.8-V to 30-V, 3-A, 200-kHz to 2.2-MHz, low-IQ synchronous buck converter in SOT-583 package 8-SOT-5X3 -40 to 150

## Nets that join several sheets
3V3: TopLevel (R32.1 R33.1), STM (21 pins), PSU (Q2.1 Q3.1 R4.2 R8.2)
+5: TopLevel (J2.02), STM (C30.2 C31.2 U7.1 U7.6), WaveGen (6 pins), PSU (R5.2 R7.2)
GND: TopLevel (J2.01 J2.03 J2.08 J7.1), STM (25 pins), WaveGen (9 pins), PSU (32 pins)
3VO_JACK: TopLevel (J5.1), PSU (C26.1 C29.1 L1.2 R26.2)
5VO: TopLevel (J6.1), PSU (C25.1 C28.1 L2.2 R29.2)
5VO_EN: STM (U1.40), PSU (U4.2)
DAC1_OUT1: STM (U1.18), WaveGen (R13.2)
I2C1_SCL: TopLevel (J2.09), STM (U1.51)
I2C1_SDA: TopLevel (J2.10), STM (U1.62)
I2C2_SCL: TopLevel (R32.2), STM (U1.22), PSU (Q3.2 R8.1)
I2C2_SDA: TopLevel (R33.2), STM (U1.42), PSU (Q2.2 R4.1)
LPUART1_RX: TopLevel (J9.2), STM (U1.17)
LPUART1_TX: TopLevel (J9.1), STM (U1.14)
NetQ6_1: STM (U1.43), WaveGen (Q6.1)
NetR9_1: STM (U1.38), PSU (R9.1 R10.1)
NetU1_39: STM (U1.39), PSU (U5.2)
PSU_OUT: TopLevel (J8.1), PSU (7 pins)
SPI_MISO: TopLevel (J2.05), STM (U1.20)
SPI_MOSI: TopLevel (J2.04), STM (U1.21)
SPI_SCK: TopLevel (J2.06), STM (U1.19)
WAV_JACK: TopLevel (J4.1), WaveGen (Q6.2)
